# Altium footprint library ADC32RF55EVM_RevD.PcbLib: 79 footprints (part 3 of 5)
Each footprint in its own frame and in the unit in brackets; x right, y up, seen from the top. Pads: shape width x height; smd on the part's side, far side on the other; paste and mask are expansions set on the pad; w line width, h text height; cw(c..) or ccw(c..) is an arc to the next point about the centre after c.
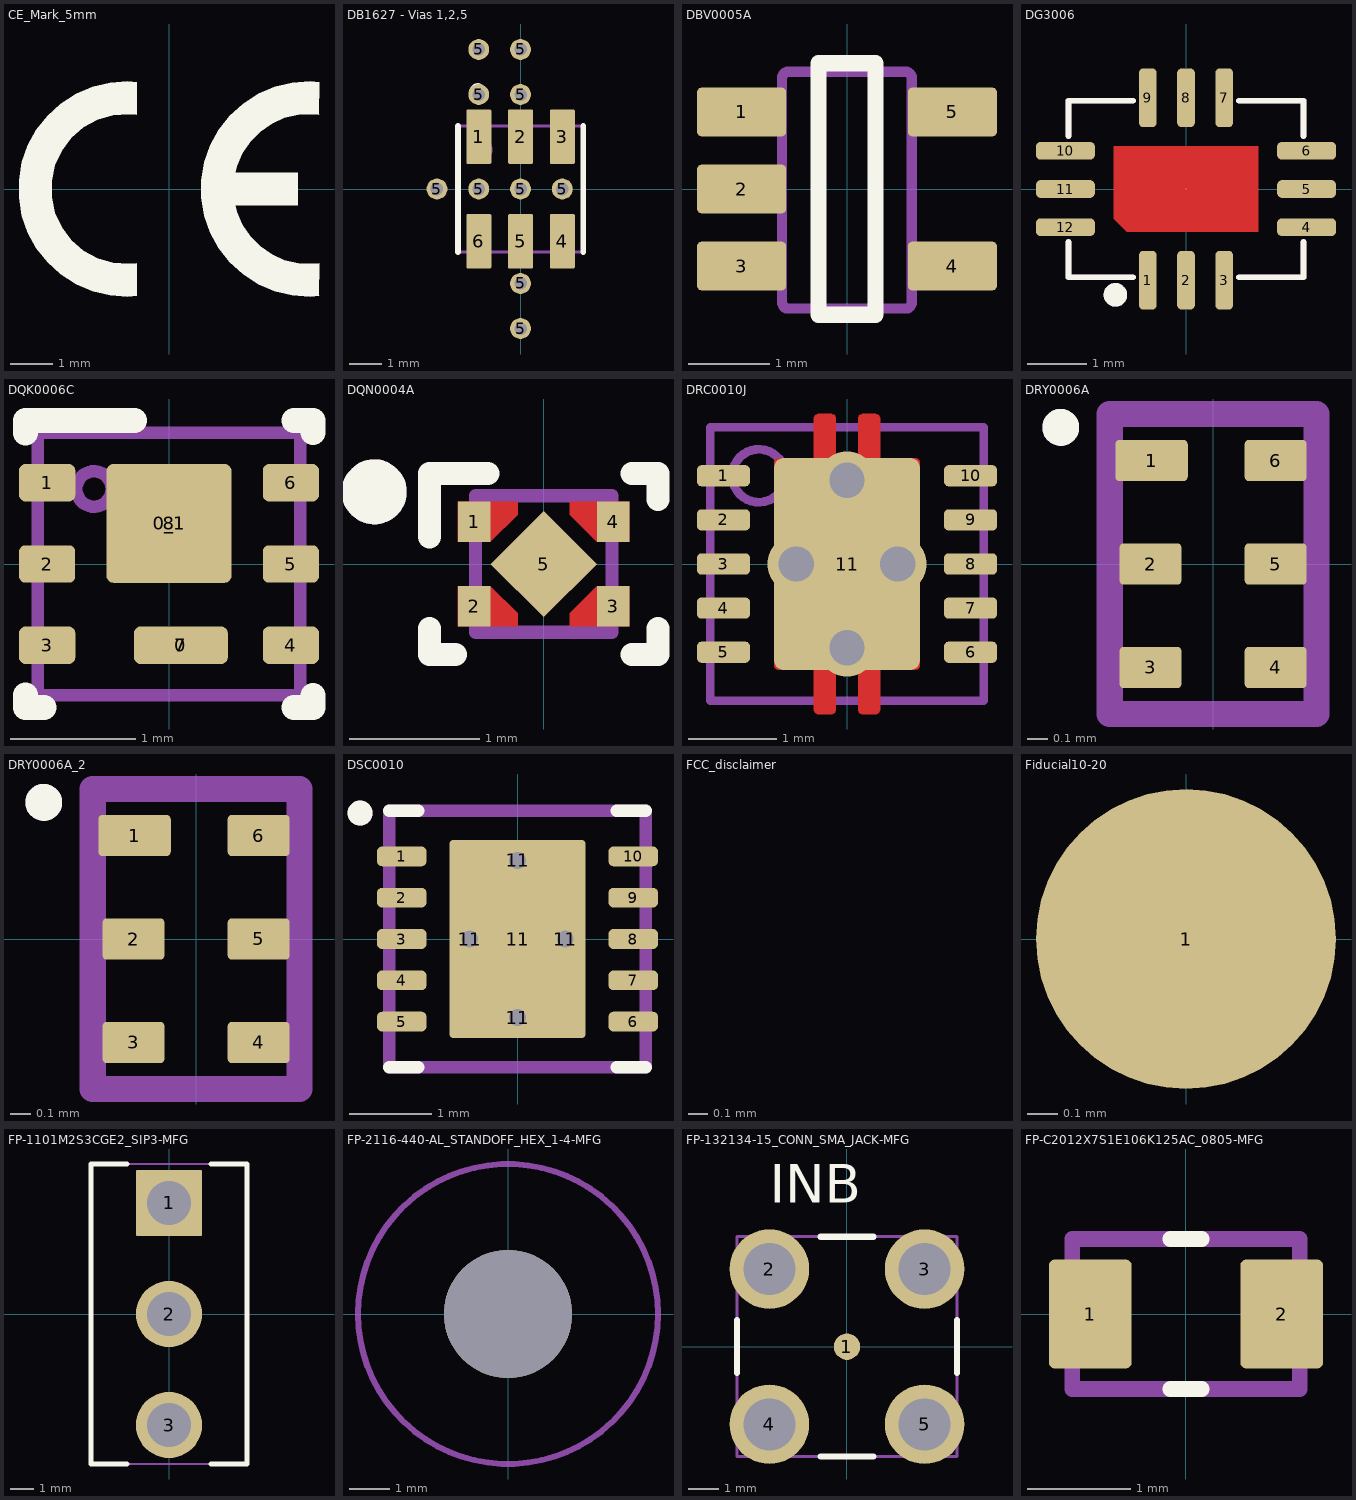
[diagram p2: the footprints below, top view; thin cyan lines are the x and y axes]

## CE_Mark_5mm [mm] "Minimum text height for CE Mark"
height 4.27
Top Overlay:
  region: 3.5,-1.732 3.337,-1.748 3.01,-1.733 2.691,-1.658 2.392,-1.525 2.123,-1.339 1.894,-1.106 1.712,-0.834 1.583,-0.533 1.541,-0.375 3,-0.375 3,0.375 1.541,0.375 1.583,0.533 1.712,0.834 1.894,1.106 2.123,1.339 2.392,1.525 2.691,1.658 3.01,1.733 3.337,1.748 3.5,1.732 3.5,2.487 3.292,2.508 2.874,2.48 2.467,2.383 2.081,2.22 1.728,1.994 1.418,1.714 1.158,1.385 0.957,1.018 0.82,0.622 0.75,0.209 0.75,-0.209 0.82,-0.622 0.957,-1.018 1.158,-1.385 1.418,-1.714 1.728,-1.994 2.081,-2.22 2.467,-2.383 2.874,-2.48 3.292,-2.508 3.5,-2.487
  region: -0.75,-2.487 -0.958,-2.508 -1.376,-2.48 -1.783,-2.383 -2.169,-2.22 -2.522,-1.994 -2.832,-1.714 -3.092,-1.385 -3.293,-1.018 -3.43,-0.622 -3.5,-0.209 -3.5,0.209 -3.43,0.622 -3.293,1.018 -3.092,1.385 -2.832,1.714 -2.522,1.994 -2.169,2.22 -1.783,2.383 -1.376,2.48 -0.958,2.508 -0.75,2.487 -0.75,1.732 -0.937,1.749 -1.31,1.722 -1.669,1.617 -1.998,1.438 -2.281,1.193 -2.505,0.893 -2.66,0.553 -2.74,0.187 -2.74,-0.187 -2.66,-0.553 -2.505,-0.893 -2.281,-1.193 -1.998,-1.438 -1.669,-1.617 -1.31,-1.722 -0.937,-1.749 -0.75,-1.732

## DB1627 - Vias 1,2,5 [mm]
height 4.06
pads (16):
  rrect10% 0.76x1.65 smd: 1(-1.27,1.59) 2(0,1.59) 3(1.27,1.59) 4(1.27,-1.59) 5(0,-1.59) 6(-1.27,-1.59)
  round 0.635 hole 0.381 mask+0.05: 5(-2.54,0) 5(-1.27,0) 5(-1.27,2.87) 5(-1.27,4.242) 5(0,0) 5(0,-4.242) 5(0,-2.87) 5(0,2.87) 5(0,4.242) 5(1.27,0)
Top Overlay:
  circle w0.25: c-1.3,2.965 r0.125
  lines w0.178: -1.905,-1.913 -1.905,1.913 ; 1.905,-1.913 1.905,1.913
Mechanical 5:
  circle w0.1: c-1.2,1.2 r0.3
  lines w0.1: -1.905,-1.913 1.905,-1.913 1.905,1.913 -1.905,1.913 -1.905,-1.913
  text ".Designator" at -0.254,0 h0.64
3D body "mini-circuits-TCM2-33WX+.step": height 3.13, standoff 0, extent -1.905,-1.905 1.905,1.905

## DBV0005A [mm] "SOT23, 5-Leads, Body 2.9x1.6mm, Pitch 0.95mm, Lead Span 2.8mm, IPC High Density"
height 1.45
pads (5):
  rrect18% 1.1x0.6 smd mask+0.07: 1(-1.3,0.95) 2(-1.3,0) 3(-1.3,-0.95) 4(1.3,-0.95) 5(1.3,0.95)
Top Overlay:
  lines w0.2: -0.35,-1.55 0.35,-1.55 0.35,1.55 -0.35,1.55 -0.35,-1.55
Mechanical 5:
  lines w0.127: -0.801,1.371 cw(c-0.725,1.37) -0.725,1.446 ; -0.801,1.37 -0.801,-1.399 -0.801,-1.4 ccw(c-0.725,-1.399) -0.725,-1.475 ; -0.801,1.37 -0.801,1.371 ; -0.725,-1.475 -0.725,-1.475 ; -0.725,-1.475 0.723,-1.475 0.724,-1.475 ccw(c0.723,-1.399) 0.799,-1.4 0.799,-1.399 0.799,1.37 ; -0.725,1.446 0.723,1.446 0.724,1.446 cw(c0.723,1.37) 0.799,1.371 ; -0.725,1.446 -0.725,1.446 ; 0.799,1.37 0.799,1.371 ; -1.423,-1.167 -1.199,-1.167 -1.105,-1.167 -1.088,-1.167 -0.835,-1.167 -0.801,-1.167 -0.801,-0.767 -0.835,-0.767 -1.088,-0.767 -1.105,-0.767 -1.199,-0.767 -1.423,-0.767 -1.423,-1.167 ; -1.423,-0.215 -1.199,-0.215 -1.105,-0.215 -1.088,-0.215 -0.835,-0.215 -0.801,-0.215 -0.801,0.186 -0.835,0.186 -1.088,0.186 -1.105,0.186 -1.199,0.186 -1.423,0.186 -1.423,-0.215 ; -1.423,0.738 -1.199,0.738 -1.105,0.738 -1.088,0.738 -0.835,0.738 -0.801,0.738 -0.801,1.138 -0.835,1.138 -1.088,1.138 -1.105,1.138 -1.199,1.138 -1.423,1.138 -1.423,0.738 ; 0.799,-1.167 0.799,-0.767 0.834,-0.767 1.087,-0.767 1.103,-0.767 1.198,-0.767 1.422,-0.767 1.422,-1.167 1.198,-1.167 1.103,-1.167 1.087,-1.167 0.834,-1.167 0.799,-1.167 ; 0.799,0.738 0.799,1.138 0.834,1.138 1.087,1.138 1.103,1.138 1.198,1.138 1.422,1.138 1.422,0.738 1.198,0.738 1.103,0.738 1.087,0.738 0.834,0.738 0.799,0.738
  text ".Designator" at -0.254,0 h0.64
3D body "DBV0005A.stp": height 1.09, standoff 0, extent -1.422,-1.46 1.422,1.461

## DG3006 [mm]
pads (13):
  rrect50% 0.3x1 smd mask+0.05: 1(-0.65,-1.55) 2(0,-1.55) 3(0.65,-1.55) 7(0.65,1.55) 8(0,1.55) 9(-0.65,1.55)
  rrect50% 1x0.3 smd mask+0.05: 4(2.05,-0.65) 5(2.05,0) 6(2.05,0.65) 10(-2.05,0.65) 11(-2.05,0) 12(-2.05,-0.65)
  round 0.025 smd mask+0.05: 13(0,0)
Top Layer:
  region: -1.008,-0.725 -1.225,-0.508 -1.225,0.725 1.225,0.725 1.225,-0.725
Top Overlay:
  circle w0.2: c-1.2,-1.8 r0.1
  lines w0.1: -2,-0.9 -2,-1.5 -0.9,-1.5 ; -2,0.9 -2,1.5 -0.9,1.5 ; 0.9,-1.5 2,-1.5 2,-0.9 ; 0.9,1.5 2,1.5 2,0.9
Mechanical 5:
  circle w0.2: c-1.2,-1.8 r0.1
  lines w0.1: -2,-0.9 -2,-1.5 -0.9,-1.5 ; -2,0.9 -2,1.5 -0.9,1.5 ; 0.9,-1.5 2,-1.5 2,-0.9 ; 0.9,1.5 2,1.5 2,0.9
  text ".Designator" at 0,0 h0.64
3D body "DG3006.step": height 0.9, standoff 0, extent -2.002,-1.502 2.002,1.502

## DQK0006C [mm] "WSON"
height 0.8
pads (10):
  rrect50% 0.7x0.29 on Top Paste: 0(0.095,-0.65)
  rrect50% 0.9x0.86 on Top Paste: 0_1(0,0.325)
  rrect33% 0.45x0.3 smd: 1(-0.975,0.65) 2(-0.975,0) 3(-0.975,-0.65) 4(0.975,-0.65) 5(0.975,0) 6(0.975,0.65)
  rrect33% 0.75x0.3 smd paste-0.15: 7(0.095,-0.65)
  rrect11% 1x0.95 smd paste-0.5: 8(0,0.325)
Top Overlay:
  lines w0.2: -1.15,-1.05 -1.15,-1.15 -1,-1.15 ; -1.15,1.05 -1.15,1.15 -0.275,1.15 ; 1,-1.15 1.15,-1.15 1.15,-1.05 ; 1,1.15 1.15,1.15 1.15,1.05
Mechanical 5:
  circle w0.1: c-0.6,0.6 r0.141
  lines w0.1: -1.05,-1.05 1.05,-1.05 1.05,1.05 -1.05,1.05 -1.05,-1.05
  text ".Designator" at -0.9,-0.4 h0.5
3D body "DQK0006C.stp": height 0.82, standoff 0, extent -1,-1 1,1

## DQN0004A [mm]
height 4.27
pads (5):
  rect 0.25x0.31 smd paste-0.142 mask-0.14: 1(-0.535,0.325) 2(-0.535,-0.325) 3(0.535,-0.325) 4(0.535,0.325)
  rect 0.58x0.58 smd rot 45 paste-0.065 mask-0.051: 5(0,0)
Top Layer:
  region: -0.66,0.17 -0.66,0.48 -0.2,0.48 -0.2,0.379 -0.409,0.17
  region: -0.66,-0.17 -0.66,-0.48 -0.2,-0.48 -0.2,-0.379 -0.409,-0.17
  region: 0.66,-0.17 0.66,-0.48 0.2,-0.48 0.2,-0.379 0.409,-0.17
  region: 0.66,0.17 0.66,0.48 0.2,0.48 0.2,0.379 0.409,0.17
Top Overlay:
  circle w0.25: c-1.303,0.555 r0.125
  lines w0.178: -0.88,-0.496 -0.88,-0.696 -0.68,-0.696 ; -0.88,0.21 -0.88,0.696 -0.43,0.696 ; 0.68,-0.696 0.88,-0.696 0.88,-0.496 ; 0.68,0.696 0.88,0.696 0.88,0.496
Top Paste:
  region: -0.65,-0.22 -0.65,-0.43 -0.25,-0.43 -0.25,-0.4 -0.43,-0.22
  region: 0.65,-0.22 0.65,-0.43 0.25,-0.43 0.25,-0.4 0.43,-0.22
  region: 0.65,0.22 0.65,0.43 0.25,0.43 0.25,0.4 0.43,0.22
  region: -0.65,0.22 -0.65,0.43 -0.25,0.43 -0.25,0.4 -0.43,0.22
Top Solder:
  region: -0.61,0.22 -0.61,0.43 -0.25,0.43 -0.25,0.4 -0.43,0.22
  region: 0.25,0.43 0.61,0.43 0.61,0.22 0.43,0.22 0.25,0.4
  region: 0.61,-0.22 0.61,-0.43 0.25,-0.43 0.25,-0.4 0.43,-0.22
  region: -0.25,-0.43 -0.61,-0.43 -0.61,-0.22 -0.43,-0.22 -0.25,-0.4
Mechanical 5:
  circle w0.25: c-1.303,0.555 r0.125
  lines w0.102: -0.525,-0.525 -0.525,0.525 0.525,0.525 0.525,-0.525 -0.525,-0.525
  text ".Designator" at 0,0 h0.51
3D body "DQN0004A.stp": height 0.37, standoff 0.01, extent -0.5,-0.5 0.5,0.5
3D body: height 0.25, standoff 0, extent 0,0 0.254,0.254

## DRC0010J [mm] "VSON-10"
height 1
pads (11):
  rrect42% 0.6x0.24 smd: 1(-1.4,1) 2(-1.4,0.5) 3(-1.4,0) 4(-1.4,-0.5) 5(-1.4,-1) 6(1.4,-1) 7(1.4,-0.5) 8(1.4,0) 9(1.4,0.5) 10(1.4,1)
  rrect12% 1.65x2.4 smd paste-1 mask-2: 11(0,0)
via 0.575,0 diameter 0.654 hole 0.4
via 0,0.95 diameter 0.654 hole 0.4
via 0,-0.95 diameter 0.654 hole 0.4
via -0.575,0 diameter 0.654 hole 0.4
Top Layer:
  region: -0.375,-1.65 -0.375,-1.2 -0.775,-1.2 -0.785,-1.2 -0.803,-1.192 -0.817,-1.178 -0.825,-1.16 -0.825,-1.15 -0.825,1.15 -0.825,1.16 -0.817,1.178 -0.803,1.192 -0.785,1.2 -0.775,1.2 -0.375,1.2 -0.375,1.65 -0.375,1.66 -0.367,1.678 -0.353,1.692 -0.335,1.7 -0.325,1.7 -0.175,1.7 -0.165,1.7 -0.147,1.692 -0.133,1.678 -0.125,1.66 -0.125,1.65 -0.125,1.2 0.125,1.2 0.125,1.65 0.125,1.66 0.133,1.678 0.147,1.692 0.165,1.7 0.175,1.7 0.325,1.7 0.335,1.7 0.353,1.692 0.367,1.678 0.375,1.66 0.375,1.65 0.375,1.2 0.775,1.2 0.785,1.2 0.803,1.192 0.817,1.178 0.825,1.16 0.825,1.15 0.825,-1.15 0.825,-1.16 0.817,-1.178 0.803,-1.192 0.785,-1.2 0.775,-1.2 0.375,-1.2 0.375,-1.65 0.375,-1.66 0.367,-1.678 0.353,-1.692 0.335,-1.7 0.325,-1.7 0.175,-1.7 0.165,-1.7 0.147,-1.692 0.133,-1.678 0.125,-1.66 0.125,-1.65 0.125,-1.2 -0.125,-1.2 -0.125,-1.65 -0.125,-1.66 -0.133,-1.678 -0.147,-1.692 -0.165,-1.7 -0.175,-1.7 -0.325,-1.7 -0.335,-1.7 -0.353,-1.692 -0.367,-1.678 -0.375,-1.66
Top Paste:
  drawing of 6 lines, arcs and shapes, not listed
Mechanical 5:
  circle w0.1: c-1,1 r0.3
  lines w0.1: -1.55,-1.55 -1.55,1.55 1.55,1.55 1.55,-1.55 -1.55,-1.55
  text ".Designator" at -1.4,-0.425 h0.76
3D body "DRC0010J.stp": height 1, standoff 0, extent -1.5,-1.5 1.5,1.5

## DRY0006A [mm]
pads (6):
  rrect20% 0.35x0.2 smd mask+0.05: 1(-0.298,0.5)
  rrect20% 0.3x0.2 smd mask+0.05: 2(-0.303,0) 3(-0.303,-0.5) 4(0.303,-0.5) 5(0.303,0) 6(0.303,0.5)
Top Overlay:
  circle w0.127: c-0.737,0.66 r0.025
Mechanical 5:
  lines w0.127: -0.5,-0.725 -0.5,0.725 0.5,0.725 0.5,-0.725 -0.5,-0.725
Mechanical 13:
  circle w0.127: c-0.737,0.66 r0.025
3D body "SN74AUP1G125DRYR.STEP": height 0.6, standoff 0, extent -0.5,-0.725 0.5,0.725

## DRY0006A_2 [mm]
pads (6):
  rrect20% 0.35x0.2 smd mask+0.05: 1(-0.298,0.5)
  rrect20% 0.3x0.2 smd mask+0.05: 2(-0.303,0) 3(-0.303,-0.5) 4(0.302,-0.5) 5(0.302,0) 6(0.302,0.5)
Top Overlay:
  circle w0.127: c-0.737,0.66 r0.025
Mechanical 5:
  lines w0.127: -0.5,-0.725 0.5,-0.725 0.5,0.725 -0.5,0.725 -0.5,-0.725
Mechanical 13:
  circle w0.127: c-0.737,0.66 r0.025
3D body "SN74AUP1G125DRYR.STEP": height 0.6, standoff 0, extent -0.5,-0.725 0.5,0.725

## DSC0010 [mm]
height 4.27
pads (15):
  rrect50% 0.6x0.24 smd paste+0 mask+0.07: 1(-1.4,1) 2(-1.4,0.5) 3(-1.4,0) 4(-1.4,-0.5) 5(-1.4,-1) 6(1.4,-1) 7(1.4,-0.5) 8(1.4,0) 9(1.4,0.5) 10(1.4,1)
  round 0.454 hole 0.2 mask+0.05: 11(-0.575,0) 11(0,-0.95) 11(0,0.95) 11(0.575,0)
  rrect6% 1.65x2.4 smd paste-1000 mask+0: 11(0,0)
Top Overlay:
  circle w0.25: c-1.905,1.524 r0.025
  lines w0.15: -1.55,-1.55 -1.2,-1.55 ; -1.55,1.55 -1.2,1.55 ; 1.2,-1.55 1.55,-1.55 ; 1.2,1.55 1.55,1.55
Top Paste:
  region: -0.7,-1.16 -0.71,-1.16 -0.728,-1.152 -0.742,-1.138 -0.75,-1.12 -0.75,-1.11 -0.75,-0.15 -0.75,-0.14 -0.742,-0.122 -0.728,-0.108 -0.71,-0.1 -0.7,-0.1 0.7,-0.1 0.71,-0.1 0.728,-0.108 0.742,-0.122 0.75,-0.14 0.75,-0.15 0.75,-1.11 0.75,-1.12 0.742,-1.138 0.728,-1.152 0.71,-1.16 0.7,-1.16
  region: 0.7,0.1 -0.7,0.1 -0.71,0.1 -0.728,0.108 -0.742,0.122 -0.75,0.14 -0.75,0.15 -0.75,1.11 -0.75,1.12 -0.742,1.138 -0.728,1.152 -0.71,1.16 -0.7,1.16 0.7,1.16 0.71,1.16 0.728,1.152 0.742,1.138 0.75,1.12 0.75,1.11 0.75,0.15 0.75,0.14 0.742,0.122 0.728,0.108 0.71,0.1
Mechanical 5:
  circle w0.25: c-1.905,1.524 r0.025
  lines w0.15: -1.55,-1.55 1.55,-1.55 1.55,1.55 -1.55,1.55 -1.55,-1.55
  text ".Designator" at -0.127,0.339 h0.64
3D body "IC_TPS7A9401DSC_WSON10.STEP": height 0.25, standoff 0, extent -1.8,-1.8 1.8,1.8

## FCC_disclaimer [mm]
Top Overlay:
  text "For evaluation only; not FCC approved for resale." at -15.57,-1.626 h1.52

## Fiducial10-20 [mm]
pads (1):
  round 1 smd paste-0.508 mask+0.203: 1(0,0)
Mechanical 5:
  text ".Designator" at -0.127,0.339 h0.64

## FP-1101M2S3CGE2_SIP3-MFG [mm]
height 4.27
pads (3):
  rrect4% 2.8x2.8 hole 1.85 paste-2539.97 mask+0: 1(0,4.7)
  round 2.8 hole 1.85 paste-2539.97 mask+0: 2(0,0) 3(0,-4.7)
Top Overlay:
  lines w0.2: -1.775,-6.35 -3.3,-6.35 -3.3,6.35 -1.775,6.35 ; 1.775,-6.35 3.3,-6.35 3.3,6.35 1.775,6.35
Mechanical 5:
  lines w0.1: -3.3,-6.35 3.3,-6.35 3.3,6.35 -3.3,6.35 -3.3,-6.35
  text ".Designator" at -0.254,0 h0.64
3D body "Switch_1101M2S3CGE2_SIP3.STEP": height 0.25, standoff 0, extent -3.4,-6.45 3.4,6.45

## FP-2116-440-AL_STANDOFF_HEX_1-4-MFG [mm]
height 4.27
pads (1):
  round 3.2 hole 3.2 unplated paste-2539.97 mask+0: ""(0,0)
Mechanical 5:
  circle w0.15: c0,0 r3.739
  text ".Designator" at -0.254,0 h0.64
3D body "PMSSS 440 0025 PH.stp": height 2.01, standoff -6.3, extent -2.781,-2.781 2.781,2.781
3D body "UNK_2116-440-AL_STANDOFF_HEX_1-4.STEP": height 31.88, standoff 0, extent -3.658,-3.175 3.658,3.175

## FP-132134-15_CONN_SMA_JACK-MFG [mm]
pads (5):
  round 0.864 smd paste+0 mask+0: 1(0,0)
  round 2.6 hole 1.7 paste-2539.97 mask+0: 2(-2.54,2.54) 3(2.54,2.54) 4(-2.54,-2.54) 5(2.54,-2.54)
Top Overlay:
  lines w0.2: -3.6,-0.865 -3.6,0.865 ; -0.865,-3.6 0.865,-3.6 ; -0.865,3.6 0.865,3.6 ; 3.6,-0.865 3.6,0.865
  text "INB" at -2.537,4.71 h1.27
Mechanical 5:
  lines w0.1: -3.6,-3.6 -3.6,3.6 3.6,3.6 3.6,-3.6 -3.6,-3.6
  text ".Designator" at -0.254,0 h0.64
3D body "Conn_132134-15_CONN_SMA_JACK.STEP": height 0.25, standoff 0, extent -3.94,-3.94 3.94,3.94

## FP-C2012X7S1E106K125AC_0805-MFG [mm]
height 4.27
pads (2):
  rrect13% 0.8x1.05 smd paste+0 mask+0: 1(-0.925,0) 2(0.925,0)
Top Overlay:
  lines w0.15: -0.15,-0.725 0.15,-0.725 ; -0.15,0.725 0.15,0.725
Mechanical 5:
  lines w0.15: -1.1,-0.725 1.1,-0.725 1.1,0.725 -1.1,0.725 -1.1,-0.725
  text ".Designator" at 0.05,0.217 h0.5
3D body "Cap_C2012X7S1E106K125AC_0805.STEP": height 0.25, standoff 0, extent -1.425,-0.825 1.425,0.825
